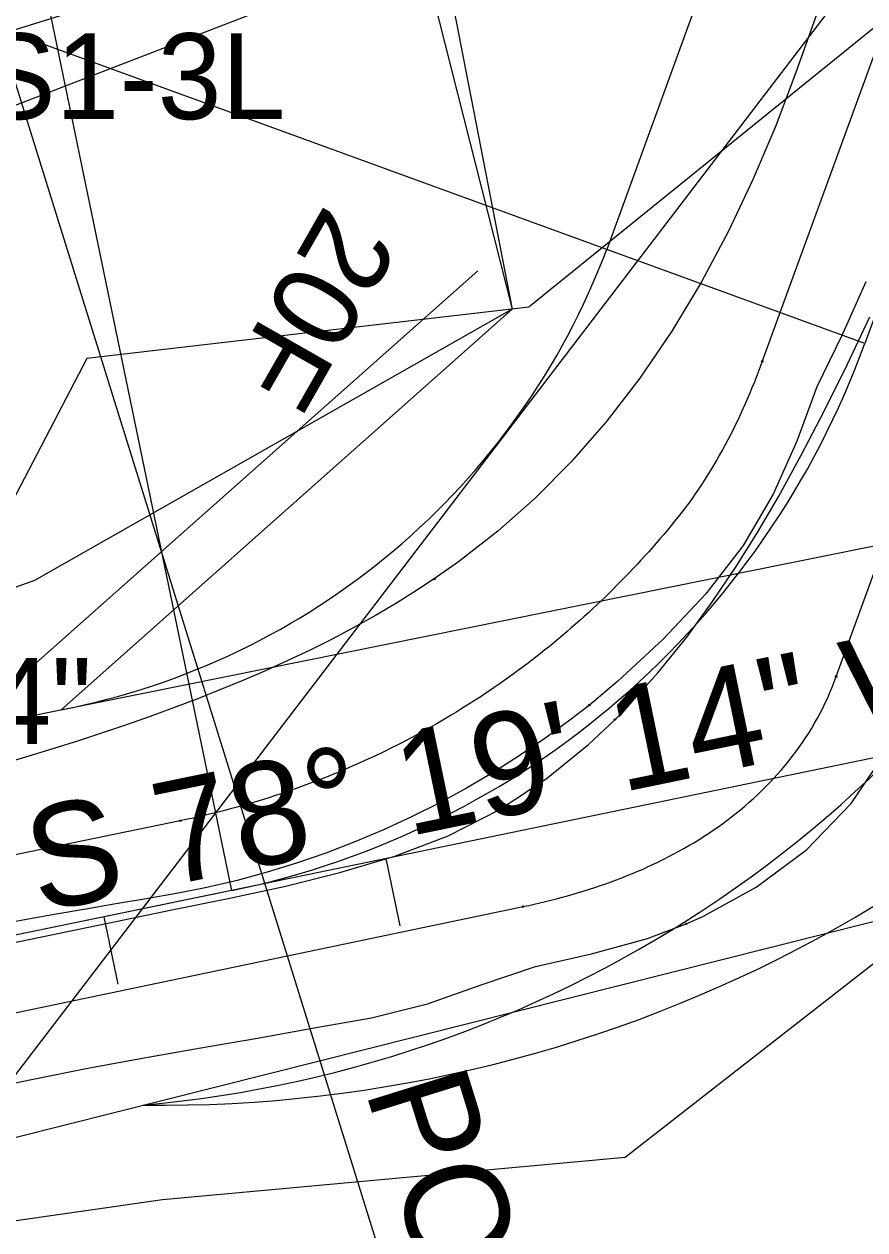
# Model space of a CAD drawing. Extents: x 2500794 to 2511032, y 910653 to 917533.
# Drawn here: x 2506053.3 to 2506102.2, y 913947.8 to 914018.1 of the extents above; entities that cross this region are included whole.
import ezdxf

# ---------------------------------------------------------------- set-up
doc = ezdxf.new("R2010")
doc.units = 0
for name, color, linetype in [('Default', 7, 'Continuous'), ('RD_EX_Driveway', 7, 'Continuous'), ('RD_EX_H2O', 7, 'Continuous'), ('RD_EX_H2O_txCode', 7, 'Continuous'), ('RD_EX_RW', 7, 'Continuous'), ('RD_EX_Wall', 7, 'Continuous'), ('RD_HC_Cl', 7, 'Continuous'), ('RD_HC_CL_Rel', 7, 'Continuous'), ('RD_HC_Data', 7, 'Continuous'), ('RD_HC_Data_Rel', 7, 'Continuous'), ('RD_HC_Data_Tic', 7, 'Continuous'), ('RD_HC_Data_Tic_Rel', 7, 'Continuous'), ('RD_PD_ALT1_TnTmp', 7, 'Continuous'), ('RD_PD_ALT2_TrvlWay', 7, 'Continuous'), ('RD_PD_CstnLmt', 7, 'Continuous'), ('RD_PD_Detour', 7, 'Continuous'), ('RD_PD_Signals', 7, 'Continuous'), ('RD_XS_NPDES', 7, 'Continuous')]:
    doc.layers.add(name, color=color, linetype=linetype)

# ---------------------------------------------------------------- blocks, each defined once
blk = doc.blocks.new('Non-Wetland Waters (Tributaries)')
at = {"layer": 'Default'}
blk.add_lwpolyline([(636463.424, 232143.109), (636471.33, 232152.976), (636485.289, 232157.041), (636505.816, 232154.48), (636536.861, 232159.182), (636555.919, 232166.539), (636568.556, 232167.887)], dxfattribs=at)

msp = doc.modelspace()

# ---------------------------------------------------------------- linework, layer by layer
at = {"layer": 'RD_EX_Driveway'}
for points in [[(2505985.767, 913963.589), (2506043.743, 913975.78), (2506109.597, 913989.049), (2506154.744, 914000.103)], [(2505819.536, 913956.764), (2505827.101, 913947.153), (2505840.353, 913935.262), (2505856.8, 913926.646), (2505912.429, 913930.556), (2505969.914, 913935.823), (2505992.802, 913939.066), (2506008.732, 913942.163), (2506105.494, 913966.503), (2506122.823, 913958.193)]]:
    msp.add_lwpolyline(points, dxfattribs=at)
at = {"layer": 'RD_EX_H2O_txCode'}
msp.add_lwpolyline([(2506111.845, 914025.213), (2506082.658, 914001.573), (2506056.908, 913998.584), (2506047.477, 913980.517), (2506043.365, 913979.626), (2505982.098, 913970.667), (2505951.963, 913982.389), (2505905.399, 913993.612), (2505873.017, 913999.745), (2505829.005, 914001.534), (2505817.694, 913986.507)], dxfattribs=at)
at = {"layer": 'RD_EX_RW'}
msp.add_line((2505954.669, 913828.579), (2506112.584, 914035.129), dxfattribs=at)
at = {"layer": 'RD_EX_Wall'}
msp.add_arc((2507719.022, 915869.797), 2585.05, 222.300975, 230.186861, dxfattribs=at)
at = {"layer": 'RD_HC_Cl'}
for p, q in [((2506112.069, 914036.227), (2506051.852, 914017.459)), ((2506172.262, 913989.702), (2505988.173, 913951.648))]:
    msp.add_line(p, q, dxfattribs=at)
at = {"layer": 'RD_HC_CL_Rel'}
for p, q in [((2506133.886, 914086.376), (2506102.227, 913999.458)), ((2506065.368, 913967.605), (2505988.173, 913951.648))]:
    msp.add_line(p, q, dxfattribs=at)
msp.add_arc((2506055.247, 914016.57), 50, 281.67952, 339.98651, dxfattribs=at)
at = {"layer": 'RD_HC_Data'}
msp.add_line((2506051.852, 914017.459), (2506088.25, 913900.676), dxfattribs=at)
at = {"layer": 'RD_HC_Data_Rel'}
for p, q in [((2506065.368, 913967.605), (2506032.496, 914126.629)), ((2506102.227, 913999.458), (2505949.957, 914054.921))]:
    msp.add_line(p, q, dxfattribs=at)
at = {"layer": 'RD_HC_Data_Tic'}
msp.add_line((2506074.333, 913969.459), (2506075.142, 913965.541), dxfattribs=at)
at = {"layer": 'RD_HC_Data_Tic_Rel'}
msp.add_line((2506057.911, 913966.064), (2506058.72, 913962.147), dxfattribs=at)
at = {"layer": 'RD_PD_ALT1_TnTmp'}
for p, q in [((2506100.556, 913980.068), (2506123.052, 914041.871)), ((2506102.713, 914016.131), (2506096.254, 913998.424)), ((2506062.361, 913971.667), (2506005.748, 913959.987)), ((2506043.389, 913958.531), (2506082.325, 913966.665))]:
    msp.add_line(p, q, dxfattribs=at)
for points in [[(2506102.829, 914027.862), (2506101.666, 914024.723), (2506100.506, 914021.585), (2506099.349, 914018.447), (2506098.217, 914015.3), (2506097.045, 914012.147), (2506095.724, 914009.049), (2506094.285, 914006.008), (2506092.712, 914003.044), (2506090.993, 914000.179), (2506089.129, 913997.442), (2506087.167, 913994.903), (2506085.125, 913992.571), (2506083.029, 913990.456), (2506080.851, 913988.524), (2506078.564, 913986.744), (2506077.145, 913985.748)], [(2506102.282, 914003.048), (2506100.903, 913999.97), (2506099.436, 913996.934), (2506098.274, 913993.78), (2506096.889, 913990.687), (2506095.132, 913987.693), (2506092.959, 913984.873), (2506090.487, 913982.248), (2506087.845, 913979.793), (2506086.183, 913978.407)], [(2506087.677, 913977.567), (2506088.289, 913978.19), (2506090.175, 913980.282), (2506091.85, 913982.367), (2506093.358, 913984.434), (2506094.732, 913986.479), (2506095.968, 913988.455), (2506097.214, 913990.577), (2506098.525, 913992.949), (2506099.861, 913995.512), (2506101.196, 913998.212), (2506102.518, 914001.02)], [(2506096.254, 913998.424), (2506096.137, 913998.111), (2506096.018, 913997.8), (2506095.897, 913997.489), (2506095.774, 913997.18), (2506095.648, 913996.871), (2506095.52, 913996.563), (2506095.389, 913996.257), (2506095.256, 913995.951), (2506095.12, 913995.647), (2506094.981, 913995.344), (2506094.839, 913995.042), (2506094.695, 913994.742), (2506094.548, 913994.443), (2506094.398, 913994.145), (2506094.244, 913993.849), (2506094.088, 913993.554), (2506093.929, 913993.262), (2506093.767, 913992.97), (2506093.602, 913992.681), (2506093.433, 913992.393), (2506093.261, 913992.108), (2506093.086, 913991.824), (2506092.908, 913991.542), (2506092.726, 913991.263), (2506092.541, 913990.985), (2506092.353, 913990.71), (2506092.161, 913990.438), (2506091.966, 913990.168), (2506091.767, 913989.9), (2506091.565, 913989.635), (2506091.36, 913989.373), (2506091.15, 913989.113), (2506090.939, 913988.855), (2506090.726, 913988.599), (2506090.512, 913988.344), (2506090.296, 913988.09), (2506090.078, 913987.838), (2506089.858, 913987.587), (2506089.637, 913987.338), (2506089.414, 913987.09), (2506089.189, 913986.844), (2506088.963, 913986.599), (2506088.735, 913986.355), (2506088.506, 913986.114), (2506088.275, 913985.873), (2506088.042, 913985.635), (2506087.808, 913985.398), (2506087.572, 913985.162), (2506087.334, 913984.928), (2506087.095, 913984.696), (2506086.855, 913984.465), (2506086.613, 913984.236), (2506086.369, 913984.008), (2506086.124, 913983.782), (2506085.878, 913983.558), (2506085.63, 913983.335), (2506085.38, 913983.114), (2506085.129, 913982.895), (2506084.877, 913982.677), (2506084.623, 913982.461), (2506084.367, 913982.247), (2506084.111, 913982.034), (2506083.852, 913981.824), (2506083.593, 913981.614), (2506083.332, 913981.407), (2506083.07, 913981.201), (2506082.806, 913980.998), (2506082.541, 913980.795), (2506082.274, 913980.595), (2506082.007, 913980.397), (2506081.738, 913980.2), (2506081.467, 913980.005), (2506081.196, 913979.812), (2506080.923, 913979.62), (2506080.648, 913979.431), (2506080.373, 913979.243), (2506080.096, 913979.057), (2506079.818, 913978.873), (2506079.539, 913978.691), (2506079.259, 913978.511), (2506078.977, 913978.332), (2506078.695, 913978.156), (2506078.411, 913977.981), (2506078.126, 913977.808), (2506077.839, 913977.637), (2506077.552, 913977.469), (2506077.263, 913977.301), (2506076.974, 913977.136), (2506076.683, 913976.973), (2506076.391, 913976.812), (2506076.099, 913976.653), (2506075.805, 913976.495), (2506075.51, 913976.34), (2506075.214, 913976.187), (2506074.917, 913976.035), (2506074.619, 913975.886), (2506074.32, 913975.738), (2506074.02, 913975.593), (2506073.719, 913975.45), (2506073.417, 913975.308), (2506073.115, 913975.169), (2506072.811, 913975.031), (2506072.506, 913974.896), (2506072.201, 913974.763), (2506071.894, 913974.631), (2506071.587, 913974.502), (2506071.279, 913974.375), (2506070.97, 913974.25), (2506070.66, 913974.127), (2506070.35, 913974.006), (2506070.038, 913973.887), (2506069.726, 913973.77), (2506069.413, 913973.655), (2506069.099, 913973.543), (2506068.785, 913973.432), (2506068.47, 913973.324), (2506068.154, 913973.217), (2506067.837, 913973.113), (2506067.52, 913973.011), (2506067.202, 913972.911), (2506066.883, 913972.813), (2506066.564, 913972.717), (2506066.244, 913972.623), (2506065.924, 913972.532), (2506065.603, 913972.442), (2506065.281, 913972.355), (2506064.959, 913972.27), (2506064.636, 913972.187), (2506064.312, 913972.106), (2506063.988, 913972.028), (2506063.664, 913971.951), (2506063.339, 913971.877), (2506063.014, 913971.805), (2506062.688, 913971.735), (2506062.361, 913971.667)], [(2506077.145, 913985.748), (2506076.182, 913985.112), (2506074.96, 913984.348), (2506073.721, 913983.618), (2506072.467, 913982.919), (2506071.199, 913982.251), (2506069.918, 913981.61), (2506068.625, 913980.995), (2506067.32, 913980.404), (2506065.996, 913979.832), (2506064.666, 913979.283), (2506063.323, 913978.752), (2506061.968, 913978.238), (2506060.601, 913977.74), (2506059.22, 913977.255), (2506057.833, 913976.785), (2506056.433, 913976.326), (2506054.998, 913975.872), (2506053.537, 913975.423), (2506052.052, 913974.981)], [(2506082.325, 913966.665), (2506082.65, 913966.735), (2506082.976, 913966.808), (2506083.3, 913966.883), (2506083.624, 913966.961), (2506083.948, 913967.041), (2506084.271, 913967.124), (2506084.593, 913967.21), (2506084.914, 913967.298), (2506085.235, 913967.39), (2506085.555, 913967.484), (2506085.874, 913967.581), (2506086.192, 913967.681), (2506086.509, 913967.784), (2506086.825, 913967.89), (2506087.14, 913967.999), (2506087.453, 913968.112), (2506087.766, 913968.228), (2506088.077, 913968.347), (2506088.387, 913968.469), (2506088.696, 913968.595), (2506089.003, 913968.724), (2506089.309, 913968.857), (2506089.613, 913968.994), (2506089.915, 913969.134), (2506090.216, 913969.278), (2506090.515, 913969.425), (2506090.812, 913969.576), (2506091.107, 913969.731), (2506091.4, 913969.89), (2506091.691, 913970.052), (2506091.98, 913970.219), (2506092.267, 913970.389), (2506092.551, 913970.564), (2506092.833, 913970.742), (2506093.112, 913970.924), (2506093.388, 913971.11), (2506093.662, 913971.3), (2506093.933, 913971.495), (2506094.201, 913971.693), (2506094.466, 913971.895), (2506094.727, 913972.101), (2506094.986, 913972.312), (2506095.241, 913972.526), (2506095.493, 913972.745), (2506095.741, 913972.968), (2506095.985, 913973.194), (2506096.226, 913973.425), (2506096.463, 913973.66), (2506096.695, 913973.898), (2506096.924, 913974.141), (2506097.148, 913974.387), (2506097.368, 913974.638), (2506097.584, 913974.892), (2506097.795, 913975.15), (2506098.001, 913975.412), (2506098.202, 913975.678), (2506098.398, 913975.948), (2506098.589, 913976.221), (2506098.775, 913976.497), (2506098.956, 913976.777), (2506099.131, 913977.061), (2506099.301, 913977.348), (2506099.465, 913977.638), (2506099.623, 913977.932), (2506099.775, 913978.228), (2506099.921, 913978.528), (2506100.061, 913978.83), (2506100.194, 913979.136), (2506100.322, 913979.444), (2506100.442, 913979.755), (2506100.556, 913980.068)], [(2506086.183, 913978.407), (2506085.045, 913977.52), (2506083.589, 913976.455), (2506082.099, 913975.439), (2506080.576, 913974.472), (2506079.021, 913973.558), (2506077.437, 913972.695), (2506075.825, 913971.886), (2506074.187, 913971.131), (2506072.524, 913970.431), (2506070.839, 913969.786), (2506069.134, 913969.198), (2506067.41, 913968.668), (2506065.669, 913968.195), (2506063.913, 913967.78), (2506062.145, 913967.425), (2506060.367, 913967.121), (2506058.603, 913966.825), (2506056.858, 913966.525), (2506055.128, 913966.223), (2506053.412, 913965.917), (2506051.708, 913965.608)], [(2506052.047, 913964.449), (2506055.324, 913965.111), (2506058.596, 913965.794), (2506061.867, 913966.478), (2506065.144, 913967.143), (2506068.416, 913967.832), (2506071.658, 913968.644), (2506074.859, 913969.598), (2506077.969, 913970.795), (2506080.924, 913972.303), (2506083.67, 913974.109), (2506086.135, 913976.112), (2506087.677, 913977.567)], [(2506091.827, 913965.666), (2506092.786, 913966.091), (2506095.903, 913967.797), (2506098.821, 913969.983), (2506101.426, 913972.669), (2506103.578, 913975.846)], [(2506050.416, 913955.913), (2506053.688, 913956.596), (2506056.965, 913957.255), (2506060.254, 913957.856), (2506063.549, 913958.439), (2506066.854, 913959.007), (2506070.16, 913959.606), (2506073.497, 913960.187), (2506076.765, 913961.001), (2506079.875, 913962.106), (2506083.047, 913963.176), (2506086.303, 913963.923), (2506089.564, 913964.819), (2506091.827, 913965.666)]]:
    msp.add_lwpolyline(points, dxfattribs=at)
for centre in [(2506096.254, 913998.424), (2506096.254, 913998.424), (2506077.145, 913985.748), (2506077.145, 913985.748), (2506100.556, 913980.068), (2506100.556, 913980.068), (2506086.183, 913978.407), (2506086.183, 913978.407), (2506087.677, 913977.567), (2506087.677, 913977.567), (2506062.361, 913971.667), (2506062.361, 913971.667), (2506082.325, 913966.665), (2506082.325, 913966.665), (2506091.827, 913965.666), (2506091.827, 913965.666)]:
    msp.add_circle(centre, 0.0417, dxfattribs=at)
at = {"layer": 'RD_PD_ALT2_TrvlWay'}
msp.add_line((2506118.852, 914091.852), (2506087.193, 914004.934), dxfattribs=at)
for centre, radius, start, end in [((2506047.28, 914020.017), 42.668, 280.99209, 339.29907), ((2506053.869, 914025.711), 70.888, 275.10424, 333.41122)]:
    msp.add_arc(centre, radius, start, end, dxfattribs=at)
at = {"layer": 'RD_PD_CstnLmt'}
for p, q in [((2506071.33, 914054.882), (2506081.683, 914001.46)), ((2506081.683, 914001.46), (2506055.416, 913978.132))]:
    msp.add_line(p, q, dxfattribs=at)
at = {"layer": 'RD_PD_Detour'}
for p, q in [((2506071.33, 914054.882), (2506081.683, 914001.46)), ((2506079.691, 914003.703), (2506053.424, 913980.375)), ((2506081.683, 914001.46), (2506055.416, 913978.132))]:
    msp.add_line(p, q, dxfattribs=at)
msp.add_arc((2506061.164, 914035.444), 80.347, 269.29562, 327.60261, dxfattribs=at)
at = {"layer": 'RD_PD_Signals'}
for p, q in [((2506067.826, 914056.158), (2506081.683, 914001.46)), ((2506081.683, 914001.46), (2506053.859, 913985.662)), ((2506053.859, 913985.662), (2506001.246, 913966.844)), ((2506122.027, 913978.4), (2506088.264, 913952.049)), ((2506088.264, 913952.049), (2506061.314, 913949.598)), ((2506061.314, 913949.598), (2506006.44, 913941.717))]:
    msp.add_line(p, q, dxfattribs=at)
at = {"layer": 'RD_XS_NPDES'}
msp.add_line((2506079.691, 914003.703), (2506053.424, 913980.375), dxfattribs=at)

# ---------------------------------------------------------------- block references
at = {"layer": 'Default', "xscale": 3.937007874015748, "yscale": 3.937007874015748}
msp.add_blockref('Non-Wetland Waters (Tributaries)', (0, 0), dxfattribs=at)
at = {"layer": 'RD_EX_H2O', "xscale": 3.937007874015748, "yscale": 3.937007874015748}
msp.add_blockref('Non-Wetland Waters (Tributaries)', (0, 0), dxfattribs=at)

# ---------------------------------------------------------------- texts
at = {"layer": 'Default'}
for s, p in [('S1-3L', (2506050.635, 914012.527)), ('S1-3L', (2506050.635, 914012.527)), ('S1-4L Culvert 24"', (2506004.675, 913976.138)), ('S1-4L Culvert 24"', (2506004.675, 913976.138))]:
    msp.add_text(s, height=5, dxfattribs=at).set_placement(p)
at = {"layer": 'RD_HC_Data'}
for s, rotation, p in [('S 78%%d 19\' 14" W', 11.67952, (2506054.129, 913966.303)), ('POT=11+85.16', 287.31083, (2506073.102, 913955.998))]:
    msp.add_text(s, height=6, rotation=rotation, dxfattribs=at).set_placement(p)
at = {"layer": 'RD_PD_CstnLmt'}
msp.add_text('20F', height=5, rotation=240.24864, dxfattribs=at).set_placement((2506070.831, 914007.663))
at = {"layer": 'RD_PD_Detour'}
msp.add_text('20F', height=5, rotation=240.24864, dxfattribs=at).set_placement((2506070.831, 914007.663))
at = {"layer": 'RD_PD_Signals'}
msp.add_text('20F', height=5, rotation=240.24864, dxfattribs=at).set_placement((2506070.831, 914007.663))

doc.saveas('drawing.dxf')
